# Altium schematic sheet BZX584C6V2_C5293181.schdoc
size 127 x 101 mm
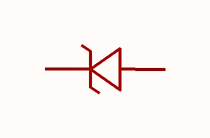
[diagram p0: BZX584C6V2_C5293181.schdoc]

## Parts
D?  bzx584c6v2_c5293181  [SOD-523_L1.2-W0.8-LS1.6-RD-1]  (value not drawn)

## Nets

Not connected (* = marked no-connect by the designer): D? 1(K) 2(A)

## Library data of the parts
D? = bzx584c6v2_c5293181: 稳压值(标称值):6.2V;稳压值(范围):5.8V~6.6V;耗散功率(Pd):150mW;; Manufacturer: CJ(江苏长电/长晶); AddInBom: yes; ModelId: d10bb3db7b4b41808fe672faecd39ab5; ModelTransform: 62.992,31.496,0,0,0,0,0,0,0; Zener Voltage(Nom): 6.2V; Reverse Leakage Current (Ir): 3uA@4V; Pd - Power Dissipation: 150mW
